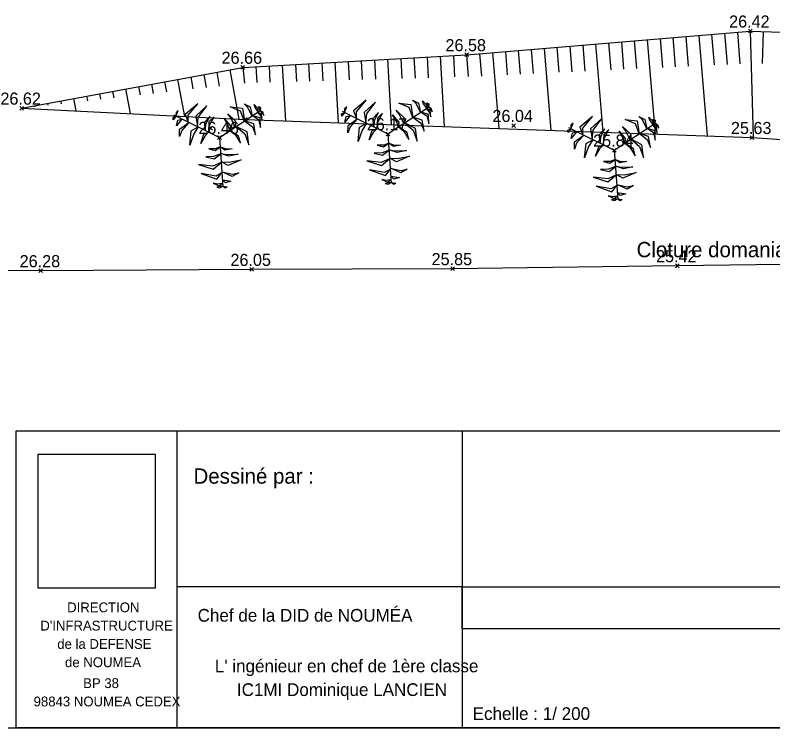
# Model space of a CAD drawing. Extents: x 37864 to 38032, y 453991 to 454052.
# Drawn here: x 37906.04 to 37923.89, y 453990.82 to 454007.62 of the extents above; entities that cross this region are included whole.
import ezdxf

# ---------------------------------------------------------------- set-up
doc = ezdxf.new("R2010")
doc.units = 0
for name, color, linetype in [('DH_CALCUL SURFACE-TEXTE', 7, 'Continuous'), ('DH_HACHURE-MOTIF', 7, 'Continuous'), ('GO_POTEAU', 7, 'Continuous'), ('PS_Const', 7, 'Continuous'), ('PS_Dim', 7, 'Continuous'), ('PS_Hidden', 7, 'Continuous')]:
    doc.layers.add(name, color=color, linetype=linetype)

# ---------------------------------------------------------------- blocks, each defined once
blk = doc.blocks.new('CONIFERE')
for p, q in [((0, 0), (0.976, 0.647)), ((-1.078, 0.532), (0, 0)), ((0, 0), (0.08, -1.165))]:
    blk.add_line(p, q)
for points in [[(-0.741, 0.364), (-0.739, 0.523), (-0.511, 0.797), (-0.811, 0.54)], [(-0.519, 0.261), (-0.499, 0.472), (-0.295, 0.746), (-0.559, 0.501)], [(0.588, 0.387), (0.498, 0.618), (0.255, 0.727), (0.538, 0.69)], [(0.768, 0.507), (0.663, 0.715), (0.579, 0.797), (0.722, 0.721)], [(0.913, 0.604), (0.84, 0.707), (0.816, 0.777), (0.899, 0.693)], [(0.956, 0.633), (0.917, 0.732), (0.966, 0.705)], [(-1.025, 0.504), (-0.971, 0.637), (-1.021, 0.589)], [(0.371, 0.242), (0.267, 0.463), (0.197, 0.562), (0.378, 0.385)], [(0.907, 0.587), (0.977, 0.501), (1.009, 0.403), (0.992, 0.558)], [(0.958, 0.634), (1.046, 0.52), (1.029, 0.588)], [(-1.023, 0.503), (-1.089, 0.42), (-1.091, 0.475)], [(-0.888, 0.436), (-1.016, 0.279), (-0.985, 0.411)], [(-0.335, 0.164), (-0.311, 0.342), (-0.22, 0.506), (-0.364, 0.356)], [(-0.262, 0.122), (-0.241, 0.278), (-0.128, 0.485), (-0.248, 0.367)], [(0.245, 0.158), (0.215, 0.27), (0.111, 0.452), (0.259, 0.279)], [(0.59, 0.394), (0.775, 0.253), (0.851, 0.066), (0.809, 0.322)], [(0.782, 0.51), (0.919, 0.422), (0.966, 0.236), (0.956, 0.46)], [(-0.721, 0.354), (-0.891, 0.168), (-0.941, 0.021), (-0.939, 0.198)], [(-0.506, 0.248), (-0.606, 0.089), (-0.702, -0.183), (-0.666, 0.155)], [(0.394, 0.257), (0.593, 0.086), (0.691, -0.173), (0.65, 0.13)], [(-0.256, 0.125), (-0.338, 0.043), (-0.443, -0.139), (-0.368, 0.076)], [(0.246, 0.164), (0.37, 0.069), (0.493, -0.134), (0.451, 0.03)], [(0.018, -0.223), (-0.1, -0.27), (-0.255, -0.267), (-0.103, -0.306)], [(0.018, -0.218), (0.131, -0.256), (0.297, -0.27), (0.128, -0.295)], [(0.029, -0.381), (-0.138, -0.448), (-0.325, -0.452), (-0.124, -0.502)], [(0.029, -0.376), (0.157, -0.398), (0.437, -0.392), (0.22, -0.442)], [(0.041, -0.571), (0.229, -0.578), (0.512, -0.525), (0.202, -0.663)], [(0.037, -0.588), (-0.156, -0.676), (-0.495, -0.637), (-0.152, -0.743)], [(0.058, -0.832), (-0.08, -0.91), (-0.431, -0.849), (-0.059, -0.981)], [(0.057, -0.81), (0.303, -0.864), (0.456, -0.834), (0.301, -0.92)], [(0.069, -0.995), (0.269, -1.028), (0.14, -1.067)], [(0.064, -1.081), (-0.046, -1.098), (-0.147, -1.076), (-0.004, -1.14)], [(0.079, -1.149), (-0.063, -1.168), (0.004, -1.187)], [(0.079, -1.146), (0.184, -1.162), (0.137, -1.191)]]:
    blk.add_lwpolyline(points, close=True)
blk = doc.blocks.new('POINT_DISPLAY')
for p, q in [((-0.04375, -0.04375), (0.04375, 0.04375)), ((-0.04375, 0.04375), (0.04375, -0.04375))]:
    blk.add_line(p, q)
blk = doc.blocks.new('POINTCOT')
blk.add_blockref('POINT_DISPLAY', (0, 0))

msp = doc.modelspace()

# ---------------------------------------------------------------- linework, layer by layer
at = {"layer": 'DEFPOINTS'}
for p, q in [((37909.85, 453997.816), (37909.85, 453990.816)), ((37916.578, 453997.816), (37916.578, 453990.816)), ((37916.578, 453994.139), (37909.85, 453994.139))]:
    msp.add_line(p, q, dxfattribs=at)
for points in [[(37864.064, 453990.816), (37946.064, 453990.816), (37946.064, 454048.216), (37864.064, 454048.216)], [(37906.064, 453997.816), (37946.064, 453997.816), (37946.064, 453990.816), (37906.064, 453990.816)], [(37906.58, 453994.116), (37909.349, 453994.116), (37909.349, 453997.261), (37906.58, 453997.261)], [(37916.578, 453994.139), (37931.232, 453994.139), (37931.232, 453993.149), (37916.578, 453993.149)]]:
    msp.add_lwpolyline(points, close=True, dxfattribs=at)
at = {"layer": 'DH_HACHURE-MOTIF'}
for p, q in [((37922.754, 454007.19), (37922.816, 454006.457)), ((37923.058, 454007.216), (37923.12, 454006.472)), ((37923.362, 454007.241), (37923.428, 454004.73)), ((37923.665, 454007.232), (37923.641, 454006.478)), ((37920.628, 454007.013), (37920.683, 454006.356)), ((37920.932, 454007.038), (37921.118, 454004.813)), ((37921.236, 454007.064), (37921.293, 454006.385)), ((37921.54, 454007.089), (37921.597, 454006.4)), ((37921.843, 454007.114), (37921.902, 454006.414)), ((37922.147, 454007.14), (37922.345, 454004.769)), ((37922.451, 454007.165), (37922.511, 454006.443)), ((37918.503, 454006.835), (37918.664, 454004.902)), ((37918.806, 454006.861), (37918.856, 454006.27)), ((37919.11, 454006.886), (37919.16, 454006.284)), ((37919.414, 454006.911), (37919.465, 454006.299)), ((37919.717, 454006.937), (37919.891, 454004.858)), ((37920.021, 454006.962), (37920.074, 454006.327)), ((37920.325, 454006.988), (37920.379, 454006.342)), ((37916.37, 454006.666), (37916.398, 454006.16)), ((37916.68, 454006.683), (37916.716, 454006.169)), ((37916.984, 454006.709), (37917.028, 454006.183)), ((37917.288, 454006.734), (37917.437, 454004.946)), ((37917.592, 454006.759), (37917.637, 454006.212)), ((37917.895, 454006.785), (37917.942, 454006.226)), ((37918.199, 454006.81), (37918.246, 454006.241)), ((37912.956, 454006.474), (37912.979, 454006.063)), ((37913.267, 454006.492), (37913.29, 454006.072)), ((37913.577, 454006.509), (37913.657, 454005.082)), ((37913.887, 454006.526), (37913.912, 454006.09)), ((37914.198, 454006.544), (37914.223, 454006.099)), ((37914.508, 454006.561), (37914.534, 454006.107)), ((37914.818, 454006.579), (37914.905, 454005.037)), ((37915.129, 454006.596), (37915.155, 454006.125)), ((37915.439, 454006.614), (37915.466, 454006.134)), ((37915.749, 454006.631), (37915.777, 454006.143)), ((37916.06, 454006.648), (37916.153, 454004.992)), ((37911.098, 454006.33), (37911.313, 454005.168)), ((37911.405, 454006.387), (37911.449, 454006.018)), ((37911.715, 454006.405), (37911.736, 454006.028)), ((37912.025, 454006.422), (37912.047, 454006.037)), ((37912.336, 454006.439), (37912.409, 454005.127)), ((37912.646, 454006.457), (37912.669, 454006.054)), ((37910.179, 454006.16), (37910.231, 454005.877)), ((37910.485, 454006.217), (37910.542, 454005.912)), ((37910.792, 454006.274), (37910.852, 454005.947)), ((37909.259, 454005.99), (37909.299, 454005.772)), ((37909.565, 454006.047), (37909.61, 454005.807)), ((37909.872, 454006.104), (37910.033, 454005.232)), ((37908.033, 454005.764), (37908.057, 454005.633)), ((37908.339, 454005.82), (37908.368, 454005.668)), ((37908.646, 454005.877), (37908.753, 454005.296)), ((37908.952, 454005.934), (37908.989, 454005.738)), ((37907.113, 454005.594), (37907.125, 454005.528)), ((37907.42, 454005.65), (37907.473, 454005.36)), ((37907.726, 454005.707), (37907.746, 454005.598)), ((37906.5, 454005.48), (37906.504, 454005.458)), ((37906.807, 454005.537), (37906.815, 454005.493))]:
    msp.add_line(p, q, dxfattribs=at)
for points in [[(37906.194, 454005.424), (37911.405, 454006.387), (37916.68, 454006.683), (37923.362, 454007.241), (37929.423, 454007.054), (37934.123, 454006.52), (37938.96, 454006.698)], [(37906.194, 454005.424), (37911.469, 454005.161), (37923.405, 454004.731), (37929.021, 454004.355), (37934.479, 454004.687), (37938.691, 454005.007)]]:
    msp.add_lwpolyline(points, dxfattribs=at)
at = {"layer": 'PS_Dim'}
msp.add_lwpolyline([(37941.48, 454001.939), (37936.614, 454001.859), (37931.557, 454001.855), (37926.585, 454001.773), (37921.641, 454001.708), (37916.353, 454001.64), (37911.614, 454001.622), (37906.648, 454001.592), (37904.746, 454001.604)], dxfattribs=at)

# ---------------------------------------------------------------- block references
at = {"layer": 'DH_CALCUL SURFACE-TEXTE', "rotation": 2.2526485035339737e-05}
for p in [(37923.362, 454007.241), (37916.68, 454006.683), (37911.405, 454006.387), (37906.194, 454005.424), (37911.469, 454005.161), (37917.786, 454005.015), (37910.648, 454004.953), (37910.858, 454004.733), (37914.826, 454004.819), (37923.405, 454004.731), (37920.159, 454004.434), (37911.614, 454001.622), (37916.353, 454001.64), (37921.641, 454001.708), (37906.648, 454001.592)]:
    msp.add_blockref('POINTCOT', p, dxfattribs=at)
at = {"layer": 'PS_Const', "rotation": 2.2526485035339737e-05}
for p in [(37914.826, 454004.819), (37910.858, 454004.733), (37920.159, 454004.434)]:
    msp.add_blockref('CONIFERE', p, dxfattribs=at)

# ---------------------------------------------------------------- texts
at = {"layer": 'DEFPOINTS'}
for s, height, p in [('Dessiné par :', 0.36, (37910.246, 453996.572)), ('DIRECTION', 0.2316, (37907.269, 453993.541)), ('Chef de la DID de NOUMÉA ', 0.3, (37910.343, 453993.319)), ("D'INFRASTRUCTURE", 0.23158, (37906.636, 453993.11)), ('de la DEFENSE', 0.23158, (37907.036, 453992.678)), ('de NOUMEA', 0.2316, (37907.219, 453992.247)), ("L' ingénieur en chef de 1ère classe", 0.3, (37910.748, 453992.126)), ('BP 38', 0.2316, (37907.645, 453991.754)), ('IC1MI Dominique LANCIEN', 0.3, (37911.268, 453991.567)), ('98843 NOUMEA CEDEX', 0.23158, (37906.479, 453991.322)), ('Echelle : 1/ 200', 0.3, (37916.823, 453991.002))]:
    msp.add_text(s, height=height, rotation=360, dxfattribs=at).set_placement(p)
at = {"layer": 'GO_POTEAU'}
for s, p in [('26.42', (37922.864, 454007.325)), ('26.58', (37916.182, 454006.767)), ('26.66', (37910.907, 454006.471)), ('26.62', (37905.696, 454005.507)), ('26.04', (37917.288, 454005.099)), ('26.46', (37910.36, 454004.817)), ('26.17', (37914.328, 454004.903)), ('25.63', (37922.907, 454004.815)), ('25.84', (37919.661, 454004.518)), ('25.85', (37915.855, 454001.724)), ('25.42', (37921.143, 454001.792)), ('26.28', (37906.15, 454001.676)), ('26.05', (37911.116, 454001.706))]:
    msp.add_text(s, height=0.285, rotation=0, dxfattribs=at).set_placement(p)
at = {"layer": 'PS_Hidden'}
msp.add_text('Cloture domaniale existante', height=0.36, rotation=360, dxfattribs=at).set_placement((37920.684, 454001.911))

doc.saveas('drawing.dxf')
